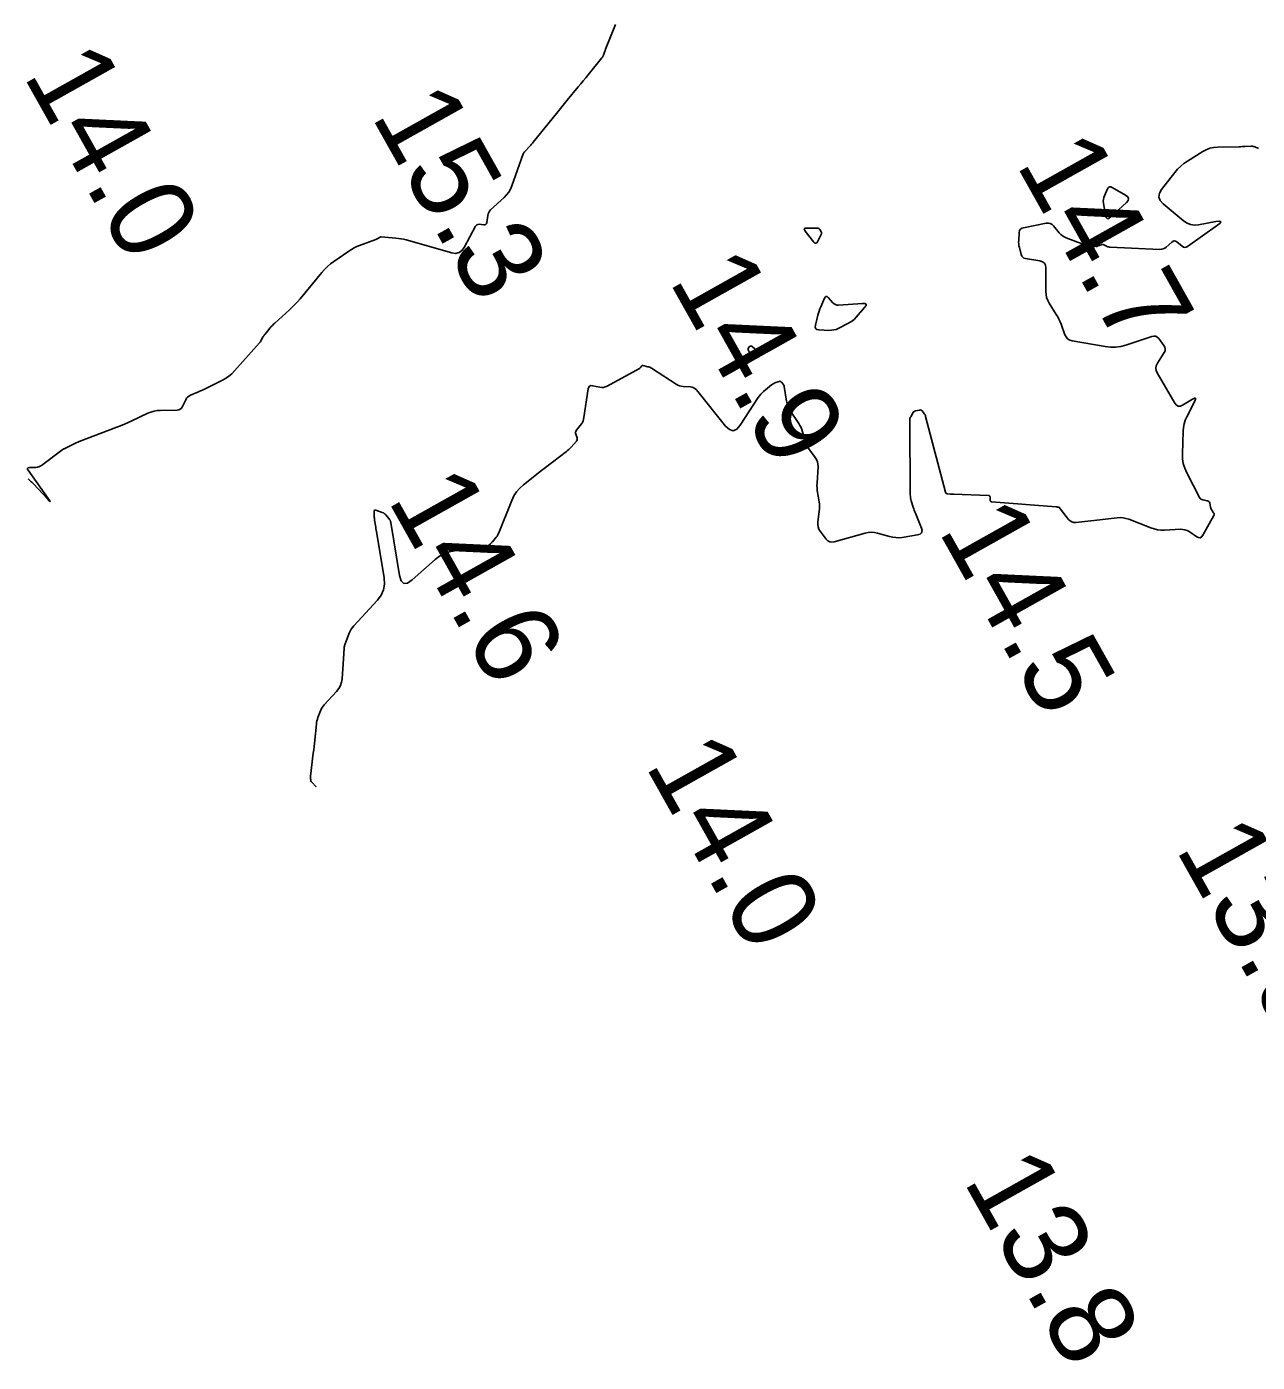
# Model space of a CAD drawing. Extents: x 1023796 to 1112670, y 656573 to 837340.
# Drawn here: x 1108735.5 to 1108808.2, y 682634.3 to 682713.2 of the extents above; entities that cross this region are included whole.
import ezdxf

# ---------------------------------------------------------------- set-up
doc = ezdxf.new("R2010")
doc.units = 0
doc.layers.add('V-CHAN-CONT-15FT', color=7, linetype='Continuous')
doc.layers.add('V-TOPO-SOUN', color=7, linetype='Continuous')

msp = doc.modelspace()

# ---------------------------------------------------------------- linework, layer by layer
at = {"layer": 'V-CHAN-CONT-15FT'}
for points in [[(1108770.251, 682713.372), (1108769.677, 682711.913), (1108769.66, 682711.87), (1108769.644, 682711.827), (1108769.627, 682711.784), (1108769.611, 682711.741), (1108769.545, 682711.569), (1108769.527, 682711.526), (1108769.505, 682711.486), (1108769.481, 682711.448), (1108769.454, 682711.411), (1108768.641, 682710.408), (1108768.496, 682710.23), (1108768.35, 682710.051), (1108768.205, 682709.872), (1108768.059, 682709.693), (1108767.405, 682708.893), (1108767.248, 682708.7), (1108767.09, 682708.507), (1108766.933, 682708.314), (1108766.776, 682708.121), (1108765.394, 682706.416), (1108765.346, 682706.358), (1108765.297, 682706.3), (1108765.247, 682706.243), (1108765.196, 682706.186), (1108764.91, 682705.871), (1108764.9, 682705.86), (1108764.89, 682705.849), (1108764.88, 682705.838), (1108764.871, 682705.827), (1108764.833, 682705.782), (1108764.824, 682705.77), (1108764.817, 682705.758), (1108764.81, 682705.745), (1108764.804, 682705.732), (1108764.133, 682703.837), (1108764.051, 682703.644), (1108763.948, 682703.464), (1108763.824, 682703.299), (1108763.678, 682703.148), (1108762.879, 682702.414), (1108762.816, 682702.345), (1108762.767, 682702.269), (1108762.733, 682702.186), (1108762.713, 682702.095), (1108762.655, 682701.672), (1108762.637, 682701.609), (1108762.604, 682701.566), (1108762.554, 682701.543), (1108762.489, 682701.539), (1108762.195, 682701.565), (1108762.126, 682701.562), (1108762.068, 682701.542), (1108762.019, 682701.503), (1108761.979, 682701.447), (1108761.322, 682700.2), (1108761.185, 682700.008), (1108761.016, 682699.891), (1108760.814, 682699.849), (1108760.58, 682699.882), (1108757.884, 682700.644), (1108757.735, 682700.682), (1108757.585, 682700.713), (1108757.433, 682700.736), (1108757.28, 682700.751), (1108756.417, 682700.816), (1108756.388, 682700.816), (1108756.36, 682700.811), (1108756.333, 682700.802), (1108756.308, 682700.787), (1108756.209, 682700.72), (1108756.184, 682700.704), (1108756.158, 682700.689), (1108756.132, 682700.677), (1108756.104, 682700.666), (1108755.142, 682700.315), (1108754.976, 682700.248), (1108754.814, 682700.171), (1108754.658, 682700.083), (1108754.507, 682699.985), (1108753.614, 682699.365), (1108753.421, 682699.221), (1108753.24, 682699.066), (1108753.069, 682698.898), (1108752.91, 682698.718), (1108751.624, 682697.162), (1108751.476, 682696.99), (1108751.322, 682696.824), (1108751.163, 682696.663), (1108750.997, 682696.508), (1108750.136, 682695.731), (1108750.062, 682695.663), (1108749.991, 682695.592), (1108749.923, 682695.518), (1108749.857, 682695.442), (1108749.533, 682695.055), (1108749.502, 682695.016), (1108749.474, 682694.976), (1108749.447, 682694.934), (1108749.423, 682694.89), (1108749.331, 682694.714), (1108749.307, 682694.67), (1108749.28, 682694.629), (1108749.25, 682694.589), (1108749.219, 682694.551), (1108747.756, 682692.907), (1108747.589, 682692.736), (1108747.408, 682692.584), (1108747.213, 682692.45), (1108747.005, 682692.334), (1108745.893, 682691.786), (1108745.802, 682691.741), (1108745.709, 682691.699), (1108745.616, 682691.657), (1108745.522, 682691.617), (1108745.146, 682691.461), (1108745.058, 682691.415), (1108744.982, 682691.356), (1108744.92, 682691.284), (1108744.869, 682691.198), (1108744.674, 682690.789), (1108744.619, 682690.702), (1108744.548, 682690.639), (1108744.462, 682690.601), (1108744.36, 682690.587), (1108743.383, 682690.571), (1108743.186, 682690.558), (1108742.994, 682690.524), (1108742.807, 682690.469), (1108742.624, 682690.395), (1108741.68, 682689.95), (1108741.462, 682689.849), (1108741.242, 682689.753), (1108741.02, 682689.662), (1108740.796, 682689.574), (1108738.573, 682688.731), (1108738.487, 682688.697), (1108738.403, 682688.66), (1108738.32, 682688.62), (1108738.238, 682688.578), (1108737.772, 682688.328), (1108737.761, 682688.323), (1108737.749, 682688.318), (1108737.738, 682688.314), (1108737.726, 682688.31), (1108737.678, 682688.297), (1108737.667, 682688.294), (1108737.655, 682688.289), (1108737.645, 682688.283), (1108737.635, 682688.276), (1108736.339, 682687.311), (1108736.262, 682687.262), (1108736.181, 682687.226), (1108736.094, 682687.204), (1108736.004, 682687.195), (1108735.632, 682687.185), (1108735.557, 682687.173), (1108735.519, 682687.143), (1108735.518, 682687.095), (1108735.554, 682687.029), (1108736.742, 682685.365), (1108736.835, 682685.23), (1108736.859, 682685.179), (1108736.814, 682685.212), (1108736.7, 682685.331), (1108735.868, 682686.232), (1108735.838, 682686.263), (1108735.808, 682686.294), (1108735.777, 682686.325), (1108735.745, 682686.354), (1108735.555, 682686.532)], [(1108808.247, 682706.049), (1108808.031, 682706.14), (1108807.976, 682706.159), (1108807.92, 682706.172), (1108807.863, 682706.179), (1108807.805, 682706.179), (1108807.435, 682706.162), (1108807.353, 682706.158), (1108807.272, 682706.155), (1108807.191, 682706.153), (1108807.109, 682706.151), (1108805.839, 682706.125), (1108805.604, 682706.105), (1108805.379, 682706.055), (1108805.162, 682705.974), (1108804.955, 682705.864), (1108804.054, 682705.306), (1108803.843, 682705.163), (1108803.648, 682705.003), (1108803.468, 682704.826), (1108803.304, 682704.632), (1108802.522, 682703.627), (1108802.391, 682703.397), (1108802.362, 682703.178), (1108802.437, 682702.971), (1108802.613, 682702.774), (1108803.791, 682701.787), (1108803.998, 682701.646), (1108804.22, 682701.558), (1108804.455, 682701.524), (1108804.705, 682701.543), (1108805.733, 682701.726), (1108805.932, 682701.747), (1108806.013, 682701.719), (1108805.976, 682701.642), (1108805.822, 682701.515), (1108804.049, 682700.254), (1108803.968, 682700.211), (1108803.887, 682700.199), (1108803.808, 682700.218), (1108803.731, 682700.267), (1108803.422, 682700.526), (1108803.345, 682700.574), (1108803.269, 682700.589), (1108803.194, 682700.57), (1108803.119, 682700.519), (1108802.789, 682700.218), (1108802.706, 682700.155), (1108802.616, 682700.111), (1108802.519, 682700.087), (1108802.414, 682700.082), (1108799.491, 682700.211), (1108799.441, 682700.215), (1108799.392, 682700.225), (1108799.345, 682700.239), (1108799.298, 682700.258), (1108799.105, 682700.35), (1108799.064, 682700.364), (1108799.024, 682700.369), (1108798.983, 682700.365), (1108798.942, 682700.353), (1108798.778, 682700.283), (1108798.737, 682700.268), (1108798.695, 682700.261), (1108798.652, 682700.259), (1108798.609, 682700.264), (1108798.005, 682700.379), (1108797.89, 682700.404), (1108797.777, 682700.433), (1108797.666, 682700.468), (1108797.556, 682700.508), (1108796.892, 682700.765), (1108796.773, 682700.82), (1108796.664, 682700.889), (1108796.565, 682700.971), (1108796.476, 682701.066), (1108796.138, 682701.476), (1108796.048, 682701.562), (1108795.946, 682701.617), (1108795.833, 682701.639), (1108795.708, 682701.629), (1108794.358, 682701.363), (1108794.257, 682701.329), (1108794.183, 682701.272), (1108794.135, 682701.191), (1108794.114, 682701.088), (1108794.078, 682700.607), (1108794.074, 682700.502), (1108794.08, 682700.397), (1108794.093, 682700.294), (1108794.116, 682700.191), (1108794.224, 682699.782), (1108794.26, 682699.69), (1108794.316, 682699.619), (1108794.391, 682699.57), (1108794.486, 682699.542), (1108795.331, 682699.402), (1108795.485, 682699.355), (1108795.595, 682699.27), (1108795.66, 682699.148), (1108795.682, 682698.988), (1108795.681, 682697.592), (1108795.693, 682697.41), (1108795.73, 682697.235), (1108795.792, 682697.067), (1108795.879, 682696.906), (1108796.299, 682696.238), (1108796.382, 682696.098), (1108796.457, 682695.954), (1108796.524, 682695.807), (1108796.583, 682695.655), (1108796.805, 682695.042), (1108796.873, 682694.905), (1108796.968, 682694.798), (1108797.089, 682694.723), (1108797.237, 682694.679), (1108799.19, 682694.337), (1108799.498, 682694.302), (1108799.803, 682694.305), (1108800.105, 682694.347), (1108800.404, 682694.426), (1108801.949, 682694.937), (1108802.065, 682694.96), (1108802.17, 682694.946), (1108802.264, 682694.897), (1108802.347, 682694.813), (1108802.656, 682694.402), (1108802.715, 682694.299), (1108802.738, 682694.194), (1108802.723, 682694.088), (1108802.673, 682693.98), (1108802.271, 682693.351), (1108802.203, 682693.209), (1108802.178, 682693.067), (1108802.198, 682692.924), (1108802.26, 682692.78), (1108803.306, 682690.994), (1108803.398, 682690.878), (1108803.505, 682690.82), (1108803.627, 682690.821), (1108803.763, 682690.879), (1108804.338, 682691.23), (1108804.454, 682691.288), (1108804.516, 682691.286), (1108804.522, 682691.225), (1108804.474, 682691.105), (1108804.011, 682690.19), (1108803.921, 682689.984), (1108803.854, 682689.772), (1108803.811, 682689.555), (1108803.791, 682689.331), (1108803.747, 682688.005), (1108803.756, 682687.713), (1108803.801, 682687.429), (1108803.883, 682687.153), (1108804.002, 682686.886), (1108804.769, 682685.416), (1108804.803, 682685.364), (1108804.846, 682685.323), (1108804.897, 682685.294), (1108804.956, 682685.276), (1108805.227, 682685.223), (1108805.277, 682685.206), (1108805.316, 682685.179), (1108805.344, 682685.14), (1108805.36, 682685.09), (1108805.409, 682684.854), (1108805.421, 682684.807), (1108805.437, 682684.762), (1108805.459, 682684.719), (1108805.484, 682684.678), (1108805.596, 682684.518), (1108805.618, 682684.478), (1108805.626, 682684.437), (1108805.622, 682684.395), (1108805.605, 682684.353), (1108804.959, 682683.187), (1108804.886, 682683.092), (1108804.802, 682683.045), (1108804.706, 682683.047), (1108804.597, 682683.099), (1108804.14, 682683.402), (1108804.023, 682683.468), (1108803.901, 682683.513), (1108803.772, 682683.537), (1108803.638, 682683.541), (1108802.683, 682683.494), (1108802.479, 682683.495), (1108802.28, 682683.516), (1108802.083, 682683.559), (1108801.89, 682683.623), (1108800.577, 682684.135), (1108800.413, 682684.188), (1108800.246, 682684.22), (1108800.076, 682684.231), (1108799.904, 682684.221), (1108799.21, 682684.138), (1108799.036, 682684.118), (1108798.863, 682684.098), (1108798.689, 682684.079), (1108798.515, 682684.06), (1108797.454, 682683.948), (1108797.329, 682683.949), (1108797.216, 682683.979), (1108797.115, 682684.039), (1108797.026, 682684.128), (1108796.551, 682684.728), (1108796.542, 682684.74), (1108796.533, 682684.751), (1108796.525, 682684.763), (1108796.516, 682684.774), (1108796.483, 682684.821), (1108796.473, 682684.831), (1108796.463, 682684.839), (1108796.451, 682684.845), (1108796.437, 682684.848), (1108796.359, 682684.857), (1108796.341, 682684.859), (1108796.323, 682684.861), (1108796.305, 682684.862), (1108796.287, 682684.864), (1108792.479, 682685.167), (1108792.44, 682685.176), (1108792.412, 682685.195), (1108792.395, 682685.224), (1108792.388, 682685.264), (1108792.385, 682685.443), (1108792.378, 682685.483), (1108792.361, 682685.511), (1108792.333, 682685.529), (1108792.293, 682685.536), (1108790.23, 682685.615), (1108790.183, 682685.617), (1108790.137, 682685.619), (1108790.091, 682685.622), (1108790.045, 682685.625), (1108789.86, 682685.638), (1108789.818, 682685.647), (1108789.785, 682685.666), (1108789.761, 682685.695), (1108789.745, 682685.735), (1108788.577, 682690.214), (1108788.563, 682690.259), (1108788.544, 682690.303), (1108788.521, 682690.344), (1108788.494, 682690.383), (1108788.376, 682690.536), (1108788.344, 682690.568), (1108788.308, 682690.587), (1108788.268, 682690.595), (1108788.223, 682690.59), (1108787.986, 682690.533), (1108787.935, 682690.516), (1108787.89, 682690.489), (1108787.852, 682690.453), (1108787.82, 682690.408), (1108787.699, 682690.195), (1108787.673, 682690.142), (1108787.655, 682690.088), (1108787.644, 682690.031), (1108787.641, 682689.972), (1108787.673, 682685.585), (1108787.677, 682685.49), (1108787.688, 682685.397), (1108787.707, 682685.304), (1108787.732, 682685.213), (1108787.847, 682684.849), (1108787.877, 682684.759), (1108787.908, 682684.669), (1108787.941, 682684.579), (1108787.976, 682684.491), (1108788.328, 682683.617), (1108788.366, 682683.46), (1108788.34, 682683.34), (1108788.25, 682683.256), (1108788.096, 682683.208), (1108787.188, 682683.065), (1108787.003, 682683.045), (1108786.819, 682683.047), (1108786.636, 682683.068), (1108786.455, 682683.11), (1108785.732, 682683.319), (1108785.551, 682683.359), (1108785.37, 682683.372), (1108785.189, 682683.359), (1108785.008, 682683.321), (1108783.174, 682682.797), (1108783.037, 682682.776), (1108782.914, 682682.795), (1108782.805, 682682.854), (1108782.709, 682682.953), (1108782.351, 682683.428), (1108782.275, 682683.551), (1108782.226, 682683.68), (1108782.205, 682683.817), (1108782.21, 682683.961), (1108782.293, 682684.61), (1108782.306, 682684.749), (1108782.308, 682684.888), (1108782.301, 682685.027), (1108782.283, 682685.165), (1108782.193, 682685.719), (1108782.175, 682685.858), (1108782.164, 682685.997), (1108782.161, 682686.136), (1108782.165, 682686.276), (1108782.222, 682687.253), (1108782.219, 682687.399), (1108782.19, 682687.537), (1108782.137, 682687.668), (1108782.059, 682687.791), (1108781.681, 682688.29), (1108781.604, 682688.402), (1108781.539, 682688.519), (1108781.487, 682688.643), (1108781.446, 682688.772), (1108781.307, 682689.301), (1108781.267, 682689.431), (1108781.217, 682689.556), (1108781.156, 682689.676), (1108781.084, 682689.792), (1108780.587, 682690.519), (1108780.504, 682690.655), (1108780.438, 682690.798), (1108780.39, 682690.947), (1108780.357, 682691.103), (1108780.226, 682691.978), (1108780.218, 682692.017), (1108780.205, 682692.053), (1108780.187, 682692.087), (1108780.163, 682692.119), (1108780.061, 682692.243), (1108780.034, 682692.268), (1108780.004, 682692.282), (1108779.971, 682692.286), (1108779.934, 682692.278), (1108779.671, 682692.187), (1108779.615, 682692.165), (1108779.563, 682692.138), (1108779.513, 682692.107), (1108779.465, 682692.071), (1108779.005, 682691.689), (1108778.917, 682691.609), (1108778.835, 682691.524), (1108778.76, 682691.432), (1108778.691, 682691.335), (1108777.624, 682689.688), (1108777.421, 682689.455), (1108777.21, 682689.369), (1108776.991, 682689.432), (1108776.764, 682689.644), (1108775.046, 682691.774), (1108774.971, 682691.85), (1108774.887, 682691.906), (1108774.793, 682691.942), (1108774.688, 682691.958), (1108774.249, 682691.985), (1108774.142, 682691.999), (1108774.039, 682692.025), (1108773.94, 682692.065), (1108773.846, 682692.118), (1108772.394, 682693.059), (1108772.342, 682693.089), (1108772.289, 682693.114), (1108772.233, 682693.135), (1108772.176, 682693.15), (1108771.872, 682693.218), (1108771.849, 682693.22), (1108771.829, 682693.216), (1108771.811, 682693.206), (1108771.796, 682693.189), (1108771.741, 682693.109), (1108771.726, 682693.09), (1108771.709, 682693.073), (1108771.691, 682693.058), (1108771.67, 682693.045), (1108769.757, 682691.995), (1108769.657, 682691.951), (1108769.554, 682691.926), (1108769.449, 682691.92), (1108769.34, 682691.934), (1108768.902, 682692.026), (1108768.803, 682692.032), (1108768.729, 682692.005), (1108768.677, 682691.944), (1108768.649, 682691.85), (1108768.397, 682690.145), (1108768.376, 682690.045), (1108768.344, 682689.95), (1108768.299, 682689.86), (1108768.242, 682689.774), (1108767.938, 682689.37), (1108767.91, 682689.322), (1108767.896, 682689.273), (1108767.895, 682689.221), (1108767.908, 682689.168), (1108767.988, 682688.949), (1108768.001, 682688.896), (1108767.999, 682688.846), (1108767.982, 682688.798), (1108767.951, 682688.753), (1108767.639, 682688.402), (1108767.573, 682688.33), (1108767.504, 682688.263), (1108767.431, 682688.198), (1108767.355, 682688.137), (1108766.535, 682687.51), (1108766.373, 682687.386), (1108766.211, 682687.261), (1108766.05, 682687.135), (1108765.889, 682687.009), (1108764.819, 682686.164), (1108764.602, 682685.969), (1108764.416, 682685.752), (1108764.26, 682685.512), (1108764.134, 682685.25), (1108763.364, 682683.339), (1108763.334, 682683.271), (1108763.299, 682683.206), (1108763.259, 682683.144), (1108763.214, 682683.084), (1108762.986, 682682.806), (1108762.957, 682682.772), (1108762.928, 682682.74), (1108762.897, 682682.709), (1108762.865, 682682.679), (1108762.736, 682682.561), (1108762.702, 682682.534), (1108762.666, 682682.514), (1108762.627, 682682.499), (1108762.584, 682682.491), (1108760.741, 682682.263), (1108760.429, 682682.201), (1108760.137, 682682.095), (1108759.865, 682681.946), (1108759.612, 682681.752), (1108758.254, 682680.545), (1108757.977, 682680.356), (1108757.76, 682680.338), (1108757.603, 682680.489), (1108757.505, 682680.809), (1108756.985, 682683.944), (1108756.97, 682684.009), (1108756.946, 682684.071), (1108756.915, 682684.129), (1108756.875, 682684.183), (1108756.699, 682684.393), (1108756.652, 682684.442), (1108756.601, 682684.483), (1108756.544, 682684.516), (1108756.481, 682684.542), (1108756.106, 682684.667), (1108756.055, 682684.677), (1108756.018, 682684.666), (1108755.997, 682684.634), (1108755.992, 682684.581), (1108756.002, 682684.33), (1108756.006, 682684.267), (1108756.011, 682684.205), (1108756.018, 682684.142), (1108756.027, 682684.08), (1108756.092, 682683.661), (1108756.106, 682683.571), (1108756.12, 682683.48), (1108756.135, 682683.39), (1108756.15, 682683.299), (1108756.587, 682680.669), (1108756.609, 682680.302), (1108756.55, 682679.959), (1108756.41, 682679.64), (1108756.189, 682679.346), (1108754.798, 682677.845), (1108754.714, 682677.745), (1108754.641, 682677.639), (1108754.578, 682677.527), (1108754.526, 682677.408), (1108754.28, 682676.764), (1108754.265, 682676.718), (1108754.252, 682676.672), (1108754.243, 682676.624), (1108754.238, 682676.576), (1108754.222, 682676.381), (1108754.218, 682676.333), (1108754.214, 682676.284), (1108754.211, 682676.235), (1108754.207, 682676.187), (1108754.101, 682674.707), (1108754.069, 682674.499), (1108754.005, 682674.306), (1108753.908, 682674.126), (1108753.779, 682673.961), (1108753.049, 682673.165), (1108752.982, 682673.085), (1108752.924, 682673), (1108752.873, 682672.91), (1108752.832, 682672.815), (1108752.681, 682672.424), (1108752.647, 682672.325), (1108752.62, 682672.225), (1108752.599, 682672.123), (1108752.585, 682672.019), (1108752.491, 682671.078), (1108752.471, 682670.886), (1108752.451, 682670.695), (1108752.429, 682670.503), (1108752.406, 682670.312), (1108752.238, 682668.948), (1108752.235, 682668.917), (1108752.234, 682668.886), (1108752.236, 682668.855), (1108752.239, 682668.824), (1108752.258, 682668.7), (1108752.265, 682668.67), (1108752.276, 682668.642), (1108752.291, 682668.616), (1108752.31, 682668.592), (1108752.567, 682668.313)]]:
    msp.add_lwpolyline(points, dxfattribs=at)
for points in [[(1108799.44, 682703.783), (1108799.517, 682703.786), (1108799.608, 682703.749), (1108800.392, 682703.294), (1108800.518, 682703.195), (1108800.567, 682703.088), (1108800.542, 682702.973), (1108800.44, 682702.85), (1108799.499, 682701.99), (1108799.392, 682701.915), (1108799.307, 682701.906), (1108799.246, 682701.965), (1108799.208, 682702.09), (1108799.084, 682702.821), (1108799.074, 682702.931), (1108799.079, 682703.038), (1108799.101, 682703.144), (1108799.139, 682703.247), (1108799.322, 682703.657), (1108799.375, 682703.74)], [(1108782.266, 682701.317), (1108782.296, 682701.294), (1108782.321, 682701.263), (1108782.41, 682701.119), (1108782.427, 682701.083), (1108782.434, 682701.047), (1108782.431, 682701.01), (1108782.417, 682700.972), (1108782.192, 682700.532), (1108782.146, 682700.466), (1108782.096, 682700.441), (1108782.042, 682700.455), (1108781.983, 682700.51), (1108781.465, 682701.155), (1108781.415, 682701.237), (1108781.413, 682701.295), (1108781.46, 682701.33), (1108781.555, 682701.341), (1108782.191, 682701.335), (1108782.231, 682701.33)], [(1108784.252, 682695.862), (1108784.127, 682695.775), (1108783.992, 682695.7), (1108783.418, 682695.414), (1108783.286, 682695.358), (1108783.15, 682695.32), (1108783.01, 682695.299), (1108782.867, 682695.296), (1108782.283, 682695.319), (1108782.162, 682695.341), (1108782.086, 682695.397), (1108782.054, 682695.486), (1108782.068, 682695.608), (1108782.22, 682696.195), (1108782.254, 682696.319), (1108782.293, 682696.441), (1108782.337, 682696.561), (1108782.386, 682696.68), (1108782.611, 682697.203), (1108782.655, 682697.275), (1108782.705, 682697.305), (1108782.763, 682697.292), (1108782.827, 682697.237), (1108783.096, 682696.93), (1108783.168, 682696.863), (1108783.248, 682696.818), (1108783.337, 682696.794), (1108783.434, 682696.791), (1108784.854, 682696.893), (1108784.996, 682696.887), (1108785.063, 682696.845), (1108785.057, 682696.765), (1108784.976, 682696.648), (1108784.475, 682696.072), (1108784.368, 682695.961)], [(1108778.18, 682694.344), (1108778.193, 682694.35), (1108778.207, 682694.354), (1108778.269, 682694.364), (1108778.284, 682694.364), (1108778.298, 682694.362), (1108778.312, 682694.357), (1108778.324, 682694.348), (1108778.49, 682694.209), (1108778.514, 682694.181), (1108778.525, 682694.152), (1108778.522, 682694.121), (1108778.506, 682694.088), (1108778.349, 682693.863), (1108778.317, 682693.828), (1108778.286, 682693.818), (1108778.258, 682693.832), (1108778.232, 682693.872), (1108778.101, 682694.143), (1108778.093, 682694.165), (1108778.091, 682694.186), (1108778.095, 682694.206), (1108778.104, 682694.227), (1108778.161, 682694.323), (1108778.169, 682694.335)]]:
    msp.add_lwpolyline(points, close=True, dxfattribs=at)

# ---------------------------------------------------------------- texts
at = {"layer": 'V-TOPO-SOUN'}
for s, p in [('14.0 ', (1108735.225, 682710.396)), ('15.3 ', (1108755.792, 682707.993)), ('14.7 ', (1108793.882, 682705.143)), ('14.9 ', (1108773.382, 682698.253)), ('14.6 ', (1108756.755, 682685.325)), ('14.5 ', (1108789.289, 682683.488)), ('14.0 ', (1108771.965, 682669.616)), ('13.9 ', (1108803.302, 682664.683)), ('13.8 ', (1108790.762, 682645.063))]:
    msp.add_text(s, height=5, rotation=299.30014, dxfattribs=at).set_placement(p)

doc.saveas('drawing.dxf')
